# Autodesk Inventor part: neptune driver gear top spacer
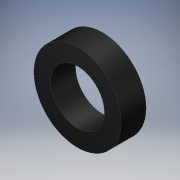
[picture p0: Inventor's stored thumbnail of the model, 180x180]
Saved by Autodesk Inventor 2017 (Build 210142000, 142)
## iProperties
Created: 2016-07
Part Number: neptune driver gear top spacer
Material: Generic
Document SubType Name: Modeling
Designer: Stan
Density: 1 g/cm^3
Appearance: Glossy - Black
Author: Stan
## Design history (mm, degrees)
sketch "Sketch1"
  geometry: C1 r 3.429 at (0, 0); C2 r 5.556 at (0, 0); 1 further point
  constraints: 2 centre point, 2 coincident
  dimensions: "d0" = 6.858 diameter of C1; "d1" = 11.1125 diameter of C2
extrude "Extrusion1" new body sketch "Sketch1" distance "d2" = 3.175; taper "d3" = 0 deg
body "Solid1"
